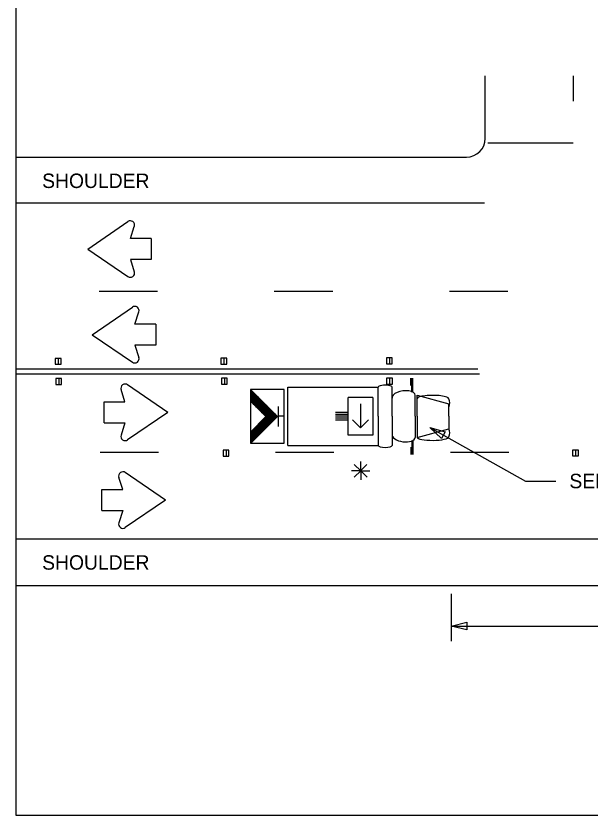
# Model space of a CAD drawing. Extents: x 1807779 to 1818251, y 673292 to 678849.
# Drawn here: x 1816600.6 to 1816839.1, y 676379.9 to 676711.9 of the extents above; entities that cross this region are included whole.
import ezdxf

# ---------------------------------------------------------------- set-up
doc = ezdxf.new("R2010")
doc.units = 0
for name, color, linetype in [('DSN_DRFT_Guideline-No-Plot', 7, 'Continuous'), ('DSN_RDWY_Drive', 7, 'Continuous'), ('Level 1', 7, 'Continuous')]:
    doc.layers.add(name, color=color, linetype=linetype)

msp = doc.modelspace()

# ---------------------------------------------------------------- linework, layer by layer
at = {"layer": 'DSN_DRFT_Guideline-No-Plot'}
msp.add_lwpolyline([(1816600.63, 676379.88), (1818250.63, 676379.88), (1818250.63, 677429.88), (1816600.63, 677429.88)], close=True, dxfattribs=at)
at = {"layer": 'DSN_RDWY_Drive'}
for p, q in [((1816795.53, 676661.03), (1816795.53, 676687.02)), ((1816796.6, 676659.16), (1816832.06, 676659.16)), ((1816600.63, 676653.27), (1816787.77, 676653.27)), ((1816600.63, 676634.33), (1816795.2, 676634.33)), ((1816630.44, 676615.07), (1816647.11, 676626.51)), ((1816648.16, 676619.44), (1816649.79, 676624.51)), ((1816656.84, 676619.44), (1816648.16, 676619.44)), ((1816656.84, 676619.44), (1816656.84, 676610.71)), ((1816630.44, 676615.07), (1816647.11, 676603.64)), ((1816656.84, 676610.71), (1816648.16, 676610.71)), ((1816648.16, 676610.71), (1816649.79, 676605.64)), ((1816632.31, 676579.49), (1816648.98, 676590.93)), ((1816650.03, 676583.86), (1816651.66, 676588.93)), ((1816658.71, 676583.86), (1816650.03, 676583.86)), ((1816658.71, 676583.86), (1816658.71, 676575.13)), ((1816632.31, 676579.49), (1816648.98, 676568.06)), ((1816658.71, 676575.13), (1816650.03, 676575.13)), ((1816650.03, 676575.13), (1816651.66, 676570.05)), ((1816619.4, 676569.61), (1816616.97, 676569.61)), ((1816616.97, 676569.61), (1816616.97, 676567.18)), ((1816618.19, 676569.61), (1816618.18, 676567.18)), ((1816619.4, 676567.18), (1816619.4, 676569.61)), ((1816685.78, 676569.72), (1816685.77, 676567.29)), ((1816688.2, 676569.72), (1816685.78, 676569.72)), ((1816687, 676569.72), (1816686.99, 676567.29)), ((1816688.2, 676567.29), (1816688.2, 676569.72)), ((1816756.95, 676569.83), (1816754.52, 676569.83)), ((1816754.52, 676569.83), (1816754.52, 676567.4)), ((1816755.74, 676569.83), (1816755.74, 676567.4)), ((1816756.95, 676567.4), (1816756.95, 676569.83)), ((1816600.63, 676565.31), (1816792.43, 676565.31)), ((1816616.97, 676567.18), (1816619.4, 676567.18)), ((1816685.77, 676567.29), (1816688.2, 676567.29)), ((1816754.52, 676567.4), (1816756.95, 676567.4)), ((1816600.63, 676563.2), (1816793.23, 676563.2)), ((1816617.18, 676561.24), (1816617.17, 676558.81)), ((1816619.6, 676561.24), (1816617.18, 676561.24)), ((1816618.39, 676561.24), (1816618.39, 676558.81)), ((1816619.6, 676558.81), (1816619.6, 676561.24)), ((1816688.41, 676561.35), (1816685.98, 676561.35)), ((1816685.98, 676561.35), (1816685.98, 676558.92)), ((1816687.2, 676561.35), (1816687.19, 676558.92)), ((1816688.41, 676558.92), (1816688.41, 676561.35)), ((1816757.03, 676561.35), (1816754.6, 676561.35)), ((1816754.6, 676561.35), (1816754.6, 676558.92)), ((1816755.82, 676561.35), (1816755.81, 676558.92)), ((1816757.03, 676558.92), (1816757.03, 676561.35)), ((1816764.6, 676558.42), (1816764.6, 676561.39)), ((1816765.07, 676555.56), (1816765.07, 676561.39)), ((1816765.47, 676555.56), (1816765.47, 676561.39)), ((1816617.17, 676558.81), (1816619.6, 676558.81)), ((1816663.64, 676547.21), (1816646.97, 676558.64)), ((1816685.98, 676558.92), (1816688.41, 676558.92)), ((1816754.6, 676558.92), (1816757.03, 676558.92)), ((1816645.91, 676551.57), (1816644.28, 676556.64)), ((1816698.07, 676556.65), (1816709.25, 676545.48)), ((1816713.55, 676557.69), (1816751.09, 676557.69)), ((1816713.55, 676533.44), (1816713.55, 676557.69)), ((1816751.09, 676545.57), (1816751.09, 676557.69)), ((1816756.85, 676545.57), (1816756.85, 676557.69)), ((1816637.24, 676542.84), (1816637.24, 676551.57)), ((1816637.24, 676551.57), (1816645.91, 676551.57)), ((1816698.07, 676551.8), (1816704.48, 676545.42)), ((1816748.89, 676553.33), (1816738.63, 676553.33)), ((1816738.63, 676537.8), (1816738.63, 676553.33)), ((1816748.89, 676553.33), (1816748.89, 676537.8)), ((1816766.48, 676545.57), (1816766.48, 676554.3)), ((1816767.28, 676554.3), (1816780.41, 676550.71)), ((1816767.28, 676545.57), (1816767.28, 676554.3)), ((1816709.63, 676541.28), (1816709.63, 676549.69)), ((1816743.76, 676550.69), (1816743.76, 676540.76)), ((1816780.41, 676545.57), (1816780.41, 676550.71)), ((1816663.64, 676547.21), (1816646.97, 676535.77)), ((1816698.07, 676539.02), (1816704.48, 676545.42)), ((1816698.13, 676534.36), (1816709.25, 676545.48)), ((1816711.96, 676545.68), (1816709.56, 676545.68)), ((1816738.63, 676547.11), (1816733.4, 676547.11)), ((1816738.63, 676546.34), (1816733.4, 676546.34)), ((1816738.63, 676545.56), (1816733.4, 676545.56)), ((1816738.63, 676544.79), (1816733.4, 676544.79)), ((1816751.09, 676545.57), (1816751.09, 676533.44)), ((1816756.85, 676545.57), (1816756.85, 676533.44)), ((1816766.48, 676545.57), (1816766.48, 676536.83)), ((1816767.28, 676545.57), (1816767.28, 676536.83)), ((1816780.41, 676545.57), (1816780.41, 676540.42)), ((1816637.24, 676542.84), (1816645.91, 676542.84)), ((1816645.91, 676542.84), (1816644.28, 676537.77)), ((1816738.63, 676544.01), (1816733.4, 676544.01)), ((1816743.76, 676540.76), (1816740.38, 676544.14)), ((1816743.76, 676540.76), (1816747.05, 676544.06)), ((1816767.28, 676536.83), (1816780.41, 676540.42)), ((1816748.89, 676537.8), (1816738.63, 676537.8)), ((1816765.07, 676535.57), (1816765.07, 676529.74)), ((1816765.47, 676535.57), (1816765.47, 676529.74)), ((1816686.66, 676531.45), (1816686.65, 676529.02)), ((1816689.08, 676531.45), (1816686.66, 676531.45)), ((1816687.87, 676531.45), (1816687.87, 676529.02)), ((1816689.08, 676529.02), (1816689.08, 676531.45)), ((1816713.55, 676533.44), (1816751.09, 676533.44)), ((1816764.6, 676532.71), (1816764.6, 676529.74)), ((1816834.24, 676531.56), (1816831.81, 676531.56)), ((1816831.81, 676531.56), (1816831.81, 676529.13)), ((1816833.03, 676531.56), (1816833.02, 676529.13)), ((1816834.24, 676529.13), (1816834.24, 676531.56)), ((1816686.65, 676529.02), (1816689.08, 676529.02)), ((1816831.81, 676529.13), (1816834.24, 676529.13)), ((1816743.83, 676522.95), (1816741.17, 676525.61)), ((1816743.76, 676522.9), (1816746.43, 676525.56)), ((1816743.83, 676522.95), (1816743.83, 676526.72)), ((1816662.71, 676510.76), (1816646.04, 676522.2)), ((1816743.83, 676522.95), (1816740.06, 676522.95)), ((1816743.83, 676522.95), (1816741.17, 676520.29)), ((1816743.83, 676522.95), (1816746.49, 676520.29)), ((1816743.83, 676522.95), (1816743.83, 676519.19)), ((1816743.83, 676522.95), (1816747.59, 676522.95)), ((1816644.99, 676515.12), (1816643.36, 676520.2)), ((1816636.31, 676506.39), (1816636.31, 676515.12)), ((1816636.31, 676515.12), (1816644.99, 676515.12)), ((1816662.71, 676510.76), (1816646.04, 676499.32)), ((1816636.31, 676506.39), (1816644.99, 676506.39)), ((1816644.99, 676506.39), (1816643.36, 676501.32)), ((1816600.63, 676494.67), (1817400.69, 676494.67)), ((1816600.63, 676475.28), (1817400.69, 676475.28)), ((1816781.4, 676471.81), (1816781.4, 676452.14)), ((1816781.4, 676458.4), (1817098.37, 676458.4)), ((1816781.4, 676458.4), (1816786.83, 676458.4))]:
    msp.add_line(p, q, dxfattribs=at)
for points in [[(1816832.02, 676687.02), (1816832.02, 676676.55)], [(1816635.17, 676597.59), (1816659.42, 676597.59)], [(1816707.92, 676597.59), (1816732.18, 676597.59)], [(1816780.68, 676597.59), (1816804.93, 676597.59)], [(1816698.07, 676556.13), (1816703.97, 676545.91)], [(1816698.07, 676555.26), (1816702.8, 676547.05)], [(1816698.57, 676556.16), (1816706.38, 676542.62)], [(1816699.76, 676554.96), (1816706.7, 676542.94)], [(1816698.07, 676554.37), (1816701.63, 676548.2)], [(1816698.07, 676553.5), (1816700.46, 676549.35)], [(1816698.07, 676552.61), (1816699.3, 676550.49)], [(1816698.07, 676551.73), (1816698.13, 676551.64)], [(1816700.96, 676553.77), (1816707.03, 676543.27)], [(1816702.16, 676552.56), (1816707.35, 676543.58)], [(1816703.36, 676551.37), (1816707.67, 676543.91)], [(1816704.56, 676550.16), (1816708, 676544.21)], [(1816705.76, 676548.97), (1816708.33, 676544.51)], [(1816703.69, 676544.63), (1816705.41, 676541.66)], [(1816704.01, 676544.96), (1816705.74, 676541.98)], [(1816704.34, 676545.28), (1816706.06, 676542.3)], [(1816706.96, 676547.78), (1816708.63, 676544.88)], [(1816708.06, 676546.69), (1816708.93, 676545.19)], [(1816700.47, 676541.42), (1816702.19, 676538.45)], [(1816700.8, 676541.74), (1816702.51, 676538.77)], [(1816701.12, 676542.07), (1816702.84, 676539.1)], [(1816701.44, 676542.39), (1816703.16, 676539.42)], [(1816701.75, 676542.71), (1816703.48, 676539.74)], [(1816702.08, 676543.03), (1816703.81, 676540.05)], [(1816702.4, 676543.35), (1816704.12, 676540.38)], [(1816702.72, 676543.67), (1816704.45, 676540.7)], [(1816703.05, 676544), (1816704.77, 676541.02)], [(1816703.37, 676544.32), (1816705.09, 676541.34)], [(1816698.07, 676538.55), (1816699.61, 676535.89)], [(1816698.22, 676539.17), (1816699.93, 676536.21)], [(1816698.54, 676539.5), (1816700.26, 676536.53)], [(1816698.86, 676539.81), (1816700.57, 676536.85)], [(1816699.19, 676540.14), (1816700.9, 676537.17)], [(1816699.5, 676540.46), (1816701.22, 676537.5)], [(1816699.83, 676540.78), (1816701.54, 676537.81)], [(1816700.15, 676541.1), (1816701.87, 676538.13)], [(1816698.07, 676537.67), (1816699.29, 676535.56)], [(1816698.07, 676536.79), (1816698.97, 676535.24)], [(1816698.07, 676535.91), (1816698.65, 676534.92)], [(1816698.07, 676535.03), (1816698.32, 676534.61)], [(1816635.61, 676530.6), (1816659.86, 676530.6)], [(1816708.36, 676530.6), (1816732.62, 676530.6)], [(1816781.12, 676530.6), (1816805.37, 676530.6)]]:
    msp.add_lwpolyline(points, dxfattribs=at)
for points in [[(1816698.07, 676556.65), (1816698.07, 676534.35), (1816712.01, 676534.35), (1816712.01, 676556.65)], [(1816777.36, 676536.32), (1816772.48, 676540.91), (1816778.95, 676539.15)], [(1816787.9, 676456.78), (1816781.4, 676458.4), (1816787.9, 676460.03)]]:
    msp.add_lwpolyline(points, close=True, dxfattribs=at)
for centre, radius, start, end in [((1816787.77, 676661.03), 7.76, 270, 360), ((1816648.11, 676625.05), 1.77, 342.1824, 124.4455), ((1816648.11, 676605.09), 1.77, 235.5545, 17.8176), ((1816649.98, 676589.47), 1.77, 342.1824, 124.4455), ((1816649.98, 676569.51), 1.77, 235.5545, 17.8176), ((1816645.97, 676557.18), 1.77, 55.5545, 197.8176), ((1816777.2, 676551.15), 3.64, 331.8801, 28.1199), ((1816777.2, 676538.7), 3.64, 331.8801, 28.1199), ((1816645.97, 676537.23), 1.77, 162.1824, 304.4455), ((1816645.04, 676520.74), 1.77, 55.5545, 197.8176), ((1816645.04, 676500.78), 1.77, 162.1824, 304.4455)]:
    msp.add_arc(centre, radius, start, end, dxfattribs=at)
for centre, major_axis, ratio, start_param, end_param in [((1816753.97, 676557.69), (2.88, 0), 0.269913, 0, 3.141593), ((1816761.66, 676553.7), (4.82, 0.6), 0.503092, 0, 3.141593), ((1816773.85, 676552.95), (6.56, -0.08), 0.2034, 0, 3.141593), ((1816761.66, 676537.43), (4.82, -0.6), 0.503092, 3.141593, 6.283185), ((1816773.85, 676536.91), (6.56, 0.08), 0.2034, 3.141593, 6.283185), ((1816753.97, 676533.44), (2.88, 0), 0.269913, 3.141593, 6.283185)]:
    msp.add_ellipse(centre, major_axis=major_axis, ratio=ratio, start_param=start_param, end_param=end_param, dxfattribs=at)
at = {"layer": 'Level 1'}
msp.add_lwpolyline([(1816772.48, 676540.91), (1816812.32, 676518.61), (1816824.86, 676518.61)], dxfattribs=at)

# ---------------------------------------------------------------- texts
at = {"layer": 'DSN_RDWY_Drive'}
for p in [(1816611.5, 676640.44), (1816611.5, 676481.84)]:
    msp.add_text('SHOULDER', height=6, rotation=0, dxfattribs=at).set_placement(p)
msp.add_text('SEE TRAIL/SHADOW VEHICLE A', height=6, dxfattribs=at).set_placement((1816830.5, 676515.68))

doc.saveas('drawing.dxf')
